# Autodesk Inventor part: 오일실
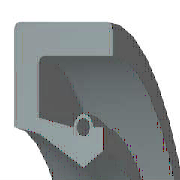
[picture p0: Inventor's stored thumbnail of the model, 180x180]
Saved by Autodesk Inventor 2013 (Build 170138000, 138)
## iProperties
IsCustomPart: 1
Created: 2015-12
Part Number: 오일실
Material: 고무
Description: 오일-실
Document SubType Name: Modeling
Standard: KS B 2804
Designer: mdu
Standards Organization: KS
Language: ko-KR
Size Designation: S - 15 30 7
Categories: <MemberInstance><Categories><Category DisplayName="샤프트 부품" InternalName="7f7aeb1f-a693-4053-b835-cee3144e0d98" Mnemonic="SHFT"><Category DisplayName="실링" Intern
Density: 0.93 g/cm^3
Mass: 1.64364 g
Surface Area: 26.6454 cm^2
Volume: 1.76736 cm^3
Author: mdu
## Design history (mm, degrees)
revolve "본체" stored, may be unused: angle "d17" = 90 deg
revolve "스프링1" stored, may be unused: angle "d18" = 90 deg
body "Solid1"
sketch "스케치1"
  geometry: L1 (0, 15)-(7, 15); L2 (7, 15)-(7, 13.75); L3 (7, 13.75)-(1.75, 13.75); L4 (0, 15)-(0, 9.6); L5 (0, 9.6)-(1.75, 9.25); L6 (1.75, 9.25)-(4.9, 7.5); L7 (4.9, 7.5)-(0, 7.5); L8 (6.3, 8.375)-(6.3, 9.6); L9 (0, 0)-(9.586, 0) reference; L10 (4.9, 7.5)-(6.3, 8.375); L11 (0, 18)-(0, -3) reference; L12 (-1.917, 0)-(11.503, 0) reference; L13 (4.2, 9.6)-(1.75, 10.09); L14 (1.75, 10.09)-(1.75, 13.75); L15 (6.3, 9.6)-(5.6, 9.6); C1 r 0.455 at (4.9, 9.6); A1 r 0.7 centre (4.9, 9.6) between (5.6, 9.6) and (4.2, 9.6)
  constraints: 26 end point, 5 horizontal alignment, 4 perpendicular, 2 centre point, 2 collinear, 2 horizontal, 2 parallel, 2 point on circle, 2 point on line, 2 vertical alignment, 1 coincident
  dimensions: "d0" = 30 diameter of L1 L9 (= SD2); "d1" = 16.75 diameter of L8.start L9 (= ABDM); "d2" = 1.25 distance of L1.end L2.end (computed from SD); "d3" = 0.91 diameter of C1 (= SPDI); "d4" = 1.4 diameter of A1 (= SPDA); "d5" = 15 diameter of L6.end L9 (= NND); "d6" = 18.5 diameter of L5.end L9 (= TKDM); "d7" = 19.2 diameter of L4.end L9 (= HLDM); "d8" = 4.9 distance from line of C1.centre L4 (= SPDST); "d9" = 6.3 distance between parallel lines of L8 L4 (= SDI); "d10" = 7 distance between parallel lines of L2 L4 (= SWDT); "d12" = 1.75 distance between parallel lines of L14 L4 (= SD)
fillet "모깎기1" dims "d11" = 0.3 (= RR)
other parameters: "SD2" = 30 [user parameter; used in 1 equation term], "SWDT" = 7 [user parameter; used in 1 equation term], "RR" = 0.3 [user parameter; used in 1 equation term], "SD" = 1.75 [user parameter; used in 2 equation terms], "NND" = 15 [user parameter; used in 1 equation term], "SPDA" = 1.4 [user parameter; used in 1 equation term], "SPDI" = 0.91 [user parameter; used in 1 equation term], "TKDM" = 18.5 [user parameter; used in 1 equation term], "HLDM" = 19.2 [user parameter; used in 1 equation term], "ABDM" = 16.75 [user parameter; used in 1 equation term], "SDI" = 6.3 [user parameter; used in 1 equation term], "SPDST" = 4.9 [user parameter; used in 1 equation term], "d13" = 0, "d14" = 0, "d15" = 0, "LAB" = 0.35 [user parameter]
